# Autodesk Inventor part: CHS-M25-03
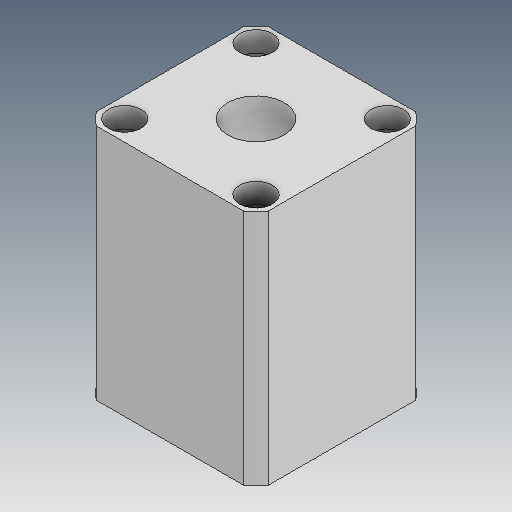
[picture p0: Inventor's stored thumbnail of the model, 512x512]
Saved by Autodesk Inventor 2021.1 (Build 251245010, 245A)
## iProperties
Created: 2019-05
Part Number: CHS-M25-03
Material: Ogólny
Document SubType Name: Modeling
Designer: user
Density: 1 g/cm^3
Appearance: Domyślna
Author: user
Revision Number: ÈÎºÎ
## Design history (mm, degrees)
feature "ÊäÈë1"
node "Bryła1"
